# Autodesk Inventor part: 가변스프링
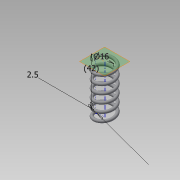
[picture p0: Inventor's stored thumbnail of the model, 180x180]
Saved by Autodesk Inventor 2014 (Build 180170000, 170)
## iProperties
Created: 2015-05
Part Number: 가변스프링
Material: Generic
Document SubType Name: Modeling
Designer: Administrator
Density: 1 g/cm^3
Appearance: Default
Author: Administrator
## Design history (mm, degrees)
sketch "스케치1"
  geometry: L1 (0, 0)-(-8, 0); L2 (-8, 0)-(-8, 41.999); L3 (-8, 41.999)-(0, 41.999); L4 (0, 41.999)-(0, 0); C1 r 1.25 at (-8, 0)
  constraints: 8 end point, 2 parallel, 1 centre point, 1 coincident, 1 horizontal, 1 perpendicular
  dimensions: "d0" = 2.5 diameter of C1; "d1" = 16 diameter of L2 L4; "d2" = 41.99913 distance between parallel lines of L3 L1 (derived)
feature "코일1" pitch "d3" = 10; turns "d5" = 6; dims "d4" = 41.99913 (= d2), "d6" = 0, angle "d7" = 90 deg, angle "d8" = 90 deg, "d9" = 0, "d10" = 0
sketch "스케치2"
  geometry: L1 (9.25, 0)-(6.75, 0) reference; 1 further point
  constraints: 1 horizontal alignment
extrude "돌출1" cut sketch "스케치2" distance "d11" = 10; taper "d12" = 0 deg
node "작업 평면1"
sketch "스케치3"
  geometry: L1 (-9.25, 0)-(-6.75, 0) reference; 1 further point
  constraints: 1 horizontal alignment
extrude "돌출2" cut sketch "스케치3" distance "d13" = 10; taper "d14" = 0 deg
node "솔리드1"
node "절단 모서리 투영1"
node "절단 모서리 투영2"
